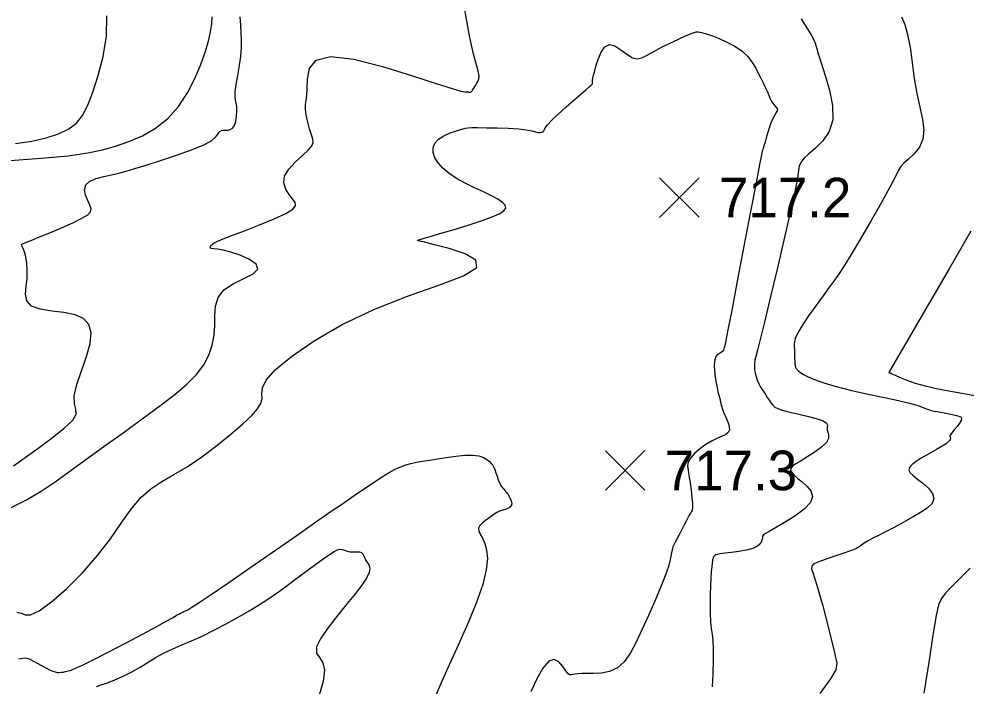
# Model space of a CAD drawing. Extents: x 2566142 to 2571431, y 418755 to 421584.
# Drawn here: x 2568476.3 to 2568835.3, y 420012.3 to 420265 of the extents above; entities that cross this region are included whole.
import ezdxf

# ---------------------------------------------------------------- set-up
doc = ezdxf.new("R2010")
doc.units = 0
for name, color, linetype in [('Contour_ADS_Major', 7, 'Continuous'), ('Contour_ADS_Minor', 7, 'Continuous'), ('Contour_ADS_Spot_Elevation', 7, 'Continuous')]:
    doc.layers.add(name, color=color, linetype=linetype)

# ---------------------------------------------------------------- blocks, each defined once
blk = doc.blocks.new('S750')
at = {"layer": 'Contour_ADS_Spot_Elevation'}
for p, q in [((-0.5, 0.498), (0.5, -0.498)), ((-0.498, -0.5), (0.498, 0.5))]:
    blk.add_line(p, q, dxfattribs=at)

msp = doc.modelspace()

# ---------------------------------------------------------------- linework, layer by layer
at = {"layer": 'Contour_ADS_Major'}
for points in [[(2568649.08, 420239.37), (2568649.47, 420239.97), (2568649.89, 420240.63), (2568650.3, 420241.37), (2568650.61, 420242.28), (2568650.69, 420243.51), (2568650.42, 420245.19), (2568649.72, 420247.61), (2568648.58, 420251.7), (2568647.04, 420258.56), (2568645.13, 420269.26)], [(2568772.83, 420265.1), (2568773.5, 420263.85), (2568774.43, 420262.35), (2568775.49, 420260.71), (2568776.55, 420259.02), (2568777.43, 420257.4), (2568778.05, 420255.89), (2568778.59, 420254.16), (2568779.28, 420251.79), (2568780.35, 420248.35), (2568781.92, 420243.6), (2568783.56, 420238.01), (2568784.68, 420232.2), (2568784.74, 420226.8), (2568783.35, 420222.33), (2568780.96, 420218.78), (2568778.2, 420216.01), (2568775.69, 420213.89), (2568773.95, 420212.28), (2568772.9, 420211.06), (2568772.34, 420210.1), (2568772.07, 420209.27), (2568771.91, 420208.45), (2568771.79, 420207.58), (2568771.67, 420206.59), (2568771.52, 420205.42), (2568771.27, 420203.88), (2568770.77, 420201.38), (2568769.86, 420197.18), (2568768.36, 420190.57), (2568766.19, 420181.2), (2568763.64, 420170.28), (2568761.07, 420159.38), (2568758.85, 420150.09), (2568757.25, 420143.61), (2568756.22, 420139.55), (2568755.61, 420137.18), (2568755.28, 420135.73), (2568755.1, 420134.55), (2568755.04, 420133.48), (2568755.09, 420132.45), (2568755.24, 420131.4), (2568755.47, 420130.28), (2568755.79, 420129.11), (2568756.2, 420127.95), (2568756.69, 420126.82), (2568757.27, 420125.76), (2568757.91, 420124.75), (2568758.58, 420123.74), (2568759.26, 420122.72), (2568759.93, 420121.66), (2568760.59, 420120.6), (2568761.28, 420119.6), (2568762, 420118.73), (2568762.82, 420118.01), (2568763.95, 420117.4), (2568765.6, 420116.8), (2568768.04, 420116.16), (2568771.34, 420115.4), (2568775.03, 420114.55), (2568778.49, 420113.66), (2568781.1, 420112.78), (2568782.44, 420111.94), (2568782.8, 420111.11), (2568782.68, 420110.27), (2568782.58, 420109.4), (2568782.85, 420108.44), (2568783.2, 420107.37), (2568783.2, 420106.11), (2568782.44, 420104.61), (2568780.64, 420102.87), (2568778.11, 420101.02)], [(2568473.18, 420079.81), (2568479.2, 420082.9), (2568484.76, 420086.18), (2568490.09, 420089.73), (2568495.59, 420093.66), (2568501.65, 420098.08), (2568508.51, 420103.03), (2568515.82, 420108.28), (2568523.05, 420113.52), (2568529.71, 420118.43), (2568535.36, 420122.8), (2568539.99, 420126.72), (2568543.65, 420130.38), (2568546.4, 420133.98), (2568548.34, 420137.64), (2568549.58, 420141.39), (2568550.26, 420145.17), (2568550.54, 420148.95), (2568550.61, 420152.68), (2568550.88, 420156.25), (2568551.85, 420159.52), (2568553.99, 420162.37), (2568557.5, 420164.73), (2568561.56, 420166.71), (2568565.04, 420168.48), (2568566.85, 420170.23), (2568566.22, 420172.07), (2568563.7, 420173.88), (2568560.2, 420175.48), (2568556.62, 420176.7), (2568553.7, 420177.41), (2568551.53, 420177.75), (2568550.05, 420177.91), (2568549.18, 420178.08), (2568548.85, 420178.4), (2568548.93, 420178.86), (2568549.31, 420179.36), (2568549.86, 420179.86), (2568550.53, 420180.3), (2568551.67, 420180.84), (2568553.69, 420181.66), (2568557.02, 420182.94), (2568561.86, 420184.78), (2568567.5, 420186.99), (2568573, 420189.26), (2568577.43, 420191.3), (2568580.08, 420192.91), (2568581.13, 420194.22), (2568580.98, 420195.46), (2568580.03, 420196.84), (2568578.69, 420198.54), (2568577.43, 420200.57), (2568576.72, 420202.88), (2568577.03, 420205.42), (2568578.65, 420208.13), (2568581.13, 420210.83), (2568583.81, 420213.32), (2568586.06, 420215.39), (2568587.38, 420216.94), (2568587.85, 420218.2), (2568587.7, 420219.49), (2568587.17, 420221.14), (2568586.48, 420223.36), (2568585.77, 420225.94), (2568585.19, 420228.54), (2568584.87, 420230.82), (2568584.9, 420232.58), (2568585.15, 420234.17), (2568585.44, 420236.06), (2568585.6, 420238.72), (2568585.65, 420242.36), (2568586.43, 420246.26), (2568589.01, 420249.4), (2568594.44, 420250.79), (2568603.28, 420249.78), (2568614.15, 420247.05), (2568625.15, 420243.64), (2568634.4, 420240.55), (2568640.5, 420238.6), (2568643.86, 420237.65), (2568645.37, 420237.36), (2568645.93, 420237.36), (2568646.27, 420237.37), (2568646.56, 420237.34), (2568646.8, 420237.29), (2568646.99, 420237.24), (2568647.15, 420237.21), (2568647.28, 420237.2), (2568647.39, 420237.21), (2568647.48, 420237.23), (2568647.57, 420237.26), (2568647.65, 420237.32), (2568647.73, 420237.4), (2568647.81, 420237.5), (2568647.92, 420237.64), (2568648.04, 420237.83), (2568648.22, 420238.08), (2568648.44, 420238.41), (2568648.73, 420238.85), (2568649.08, 420239.37)], [(2568778.11, 420101.02), (2568775.32, 420099.22), (2568772.76, 420097.66), (2568770.8, 420096.47), (2568769.5, 420095.55), (2568768.82, 420094.78), (2568768.73, 420094.02), (2568769.2, 420093.17), (2568770.14, 420092.16), (2568771.48, 420090.99), (2568773.14, 420089.63), (2568774.94, 420088.04), (2568776.44, 420086.23), (2568777.09, 420084.16), (2568776.36, 420081.83), (2568773.93, 420079.26), (2568770.37, 420076.65), (2568766.47, 420074.23), (2568763.03, 420072.25), (2568760.65, 420070.89), (2568759.25, 420070.04), (2568758.54, 420069.55), (2568758.25, 420069.27), (2568758.15, 420069.05), (2568758.12, 420068.8), (2568758.09, 420068.44), (2568758.01, 420067.89), (2568757.77, 420067.11), (2568757.23, 420066.19), (2568756.2, 420065.24), (2568754.51, 420064.4), (2568752.07, 420063.76), (2568749.2, 420063.29), (2568746.32, 420062.95), (2568743.86, 420062.68), (2568742.11, 420062.44), (2568741.02, 420062.2), (2568740.38, 420061.97), (2568740.01, 420061.73), (2568739.77, 420061.47), (2568739.6, 420061.21), (2568739.47, 420060.96), (2568739.38, 420060.74), (2568739.3, 420060.52), (2568739.22, 420060.22), (2568739.13, 420059.69), (2568739.02, 420058.83), (2568738.87, 420057.5), (2568738.71, 420055.68), (2568738.55, 420053.33), (2568738.42, 420050.41), (2568738.32, 420046.97), (2568738.28, 420043.29), (2568738.32, 420039.72), (2568738.47, 420036.6), (2568738.73, 420034.15), (2568739.04, 420031.98), (2568739.31, 420029.57), (2568739.46, 420026.38), (2568739.43, 420022.08), (2568739.26, 420017.09), (2568739.01, 420012)]]:
    msp.add_lwpolyline(points, dxfattribs=at)
at = {"layer": 'Contour_ADS_Minor'}
for points in [[(2568471.22, 420211.32), (2568484.79, 420212.23), (2568495.01, 420213.18), (2568502.39, 420214.24), (2568508, 420215.45), (2568512.91, 420216.88), (2568517.96, 420218.6), (2568523.12, 420220.78), (2568528.14, 420223.61), (2568532.76, 420227.27), (2568536.79, 420231.87), (2568540.2, 420237.08), (2568543, 420242.5), (2568545.23, 420247.73), (2568546.91, 420252.42), (2568548.11, 420256.54), (2568548.91, 420260.11), (2568549.39, 420263.16), (2568549.62, 420265.76)], [(2568475.04, 420217.84), (2568481.17, 420218.77), (2568486.64, 420219.97), (2568491.34, 420221.48), (2568495.18, 420223.32), (2568498.12, 420225.58), (2568500.42, 420228.48), (2568502.38, 420232.29), (2568504.31, 420237.26), (2568506.41, 420243.55), (2568508.31, 420250.79), (2568509.53, 420258.51), (2568509.61, 420266.23)], [(2568501.61, 420198.26), (2568501.23, 420200.32), (2568501.68, 420202.13), (2568503.24, 420203.52), (2568505.65, 420204.55), (2568508.52, 420205.33), (2568511.44, 420205.98), (2568514.15, 420206.61), (2568516.95, 420207.35), (2568520.27, 420208.32), (2568524.54, 420209.63), (2568529.98, 420211.36), (2568535.98, 420213.35), (2568541.73, 420215.41), (2568546.39, 420217.34), (2568549.39, 420218.98), (2568551, 420220.3), (2568551.73, 420221.31), (2568552.11, 420222.04), (2568552.54, 420222.49), (2568553.11, 420222.74), (2568553.81, 420222.84), (2568554.61, 420222.87), (2568555.51, 420222.89), (2568556.42, 420223.08), (2568557.28, 420223.6), (2568558, 420224.62), (2568558.52, 420226.22), (2568558.84, 420228.18), (2568558.96, 420230.18), (2568558.9, 420231.89), (2568558.68, 420233.13), (2568558.41, 420234.18), (2568558.25, 420235.45), (2568558.32, 420237.35), (2568558.71, 420240.16), (2568559.31, 420243.62), (2568559.94, 420247.33), (2568560.45, 420250.91), (2568560.7, 420254.07), (2568560.73, 420256.92), (2568560.61, 420259.69), (2568560.41, 420262.6), (2568560.19, 420265.83)], [(2568810.82, 420265.78), (2568812.04, 420262.94), (2568813.12, 420259.11), (2568814.03, 420254.17), (2568814.83, 420248.46), (2568815.65, 420242.49), (2568816.6, 420236.71), (2568817.71, 420231.53), (2568818.71, 420226.97), (2568819.23, 420222.98), (2568818.93, 420219.51), (2568817.6, 420216.5), (2568815.59, 420213.96), (2568813.41, 420211.87), (2568811.57, 420210.23), (2568810.4, 420208.95), (2568809.52, 420207.46), (2568808.38, 420205.13), (2568806.41, 420201.27), (2568803.25, 420195.54), (2568799.33, 420188.68), (2568795.29, 420181.74), (2568791.74, 420175.77), (2568789.12, 420171.51), (2568787.18, 420168.53), (2568785.47, 420166.1), (2568783.53, 420163.48), (2568781.06, 420160.13), (2568778.3, 420156.34), (2568775.61, 420152.55), (2568773.37, 420149.25), (2568771.87, 420146.79), (2568770.99, 420145.11), (2568770.56, 420144.01), (2568770.37, 420143.32), (2568770.26, 420142.86), (2568770.2, 420142.44), (2568770.17, 420141.89), (2568770.17, 420141.03), (2568770.19, 420139.74), (2568770.23, 420138.18), (2568770.29, 420136.61), (2568770.35, 420135.25), (2568770.41, 420134.29), (2568770.49, 420133.67), (2568770.58, 420133.29), (2568770.68, 420133.03), (2568770.8, 420132.81), (2568770.94, 420132.6), (2568771.08, 420132.39), (2568771.22, 420132.17), (2568771.39, 420131.94), (2568771.71, 420131.63), (2568772.35, 420131.17), (2568773.47, 420130.51), (2568775.24, 420129.59), (2568777.81, 420128.46), (2568781.36, 420127.16), (2568786.04, 420125.75), (2568791.86, 420124.29), (2568798.23, 420122.87), (2568804.41, 420121.56), (2568809.63, 420120.44), (2568813.36, 420119.59), (2568815.79, 420118.95), (2568817.33, 420118.47), (2568818.38, 420118.07), (2568819.29, 420117.7), (2568820.17, 420117.36), (2568821.07, 420117.04), (2568822.06, 420116.75), (2568823.17, 420116.49), (2568824.38, 420116.26)], [(2568693.21, 420239.96), (2568693.57, 420240.35), (2568693.72, 420240.61), (2568693.75, 420240.85), (2568693.73, 420241.18), (2568693.75, 420241.72), (2568693.86, 420242.56), (2568694.11, 420243.76), (2568694.52, 420245.38), (2568695.12, 420247.47), (2568695.93, 420249.98), (2568697, 420252.48), (2568698.37, 420254.44), (2568700.08, 420255.33), (2568702.15, 420254.82), (2568704.42, 420253.37), (2568706.7, 420251.64), (2568708.81, 420250.29), (2568710.64, 420249.84), (2568712.4, 420250.22), (2568714.38, 420251.24), (2568716.88, 420252.7), (2568720.05, 420254.39), (2568723.58, 420256.13), (2568727, 420257.71), (2568729.85, 420258.96), (2568731.82, 420259.72), (2568733.04, 420260.07), (2568733.79, 420260.14), (2568734.37, 420260.06), (2568735.01, 420259.92), (2568735.91, 420259.68), (2568737.23, 420259.27), (2568739.14, 420258.59), (2568741.7, 420257.58), (2568744.66, 420256.27), (2568747.68, 420254.67), (2568750.4, 420252.82), (2568752.58, 420250.75), (2568754.26, 420248.57), (2568755.58, 420246.37), (2568756.67, 420244.25), (2568757.66, 420242.3), (2568758.55, 420240.54), (2568759.31, 420238.97), (2568759.92, 420237.6), (2568760.37, 420236.41), (2568760.75, 420235.37), (2568761.14, 420234.45), (2568761.62, 420233.59), (2568762.25, 420232.77), (2568762.92, 420232), (2568763.47, 420231.31), (2568763.78, 420230.72), (2568763.71, 420230.22), (2568763.34, 420229.63), (2568762.74, 420228.73), (2568762, 420227.32), (2568761.2, 420225.28), (2568760.41, 420222.86), (2568759.69, 420220.43), (2568759.1, 420218.36), (2568758.67, 420216.92), (2568758.38, 420216.03), (2568758.21, 420215.54), (2568758.1, 420215.29), (2568758.01, 420214.95), (2568757.73, 420213.55), (2568757.03, 420209.93), (2568755.71, 420202.97), (2568753.63, 420192.07), (2568751.11, 420178.89), (2568748.57, 420165.63), (2568746.44, 420154.51), (2568745.03, 420147.2), (2568744.23, 420143.15), (2568743.84, 420141.29), (2568743.66, 420140.54), (2568743.5, 420140.01), (2568743.29, 420139.52), (2568742.97, 420139.07), (2568742.49, 420138.69), (2568741.83, 420138.34), (2568741.11, 420137.87), (2568740.45, 420137.1), (2568740, 420135.84), (2568739.85, 420133.98), (2568739.96, 420131.72), (2568740.23, 420129.35), (2568740.57, 420127.15), (2568740.92, 420125.32), (2568741.25, 420123.81), (2568741.59, 420122.47), (2568741.92, 420121.19), (2568742.25, 420119.85), (2568742.59, 420118.51), (2568742.94, 420117.23), (2568743.3, 420116.11), (2568743.67, 420115.17), (2568744.05, 420114.36), (2568744.44, 420113.56)], [(2568500.41, 420055.25), (2568506.11, 420061.73), (2568510.97, 420068.11), (2568515.12, 420074.06), (2568518.87, 420079.35), (2568522.52, 420083.73), (2568526.34, 420087.07), (2568530.48, 420089.79), (2568535.02, 420092.39), (2568540.07, 420095.4), (2568545.63, 420099.19), (2568551.32, 420103.47), (2568556.67, 420107.78), (2568561.21, 420111.67), (2568564.56, 420114.81), (2568566.78, 420117.29), (2568568.03, 420119.34), (2568568.48, 420121.18), (2568568.41, 420123.04), (2568568.61, 420125.25), (2568569.97, 420128.14), (2568573.42, 420132.05), (2568579.61, 420137.18), (2568588.27, 420143.1), (2568598.86, 420149.23), (2568610.86, 420155.01), (2568623.56, 420159.96), (2568635.42, 420164.15), (2568644.75, 420167.72), (2568649.82, 420170.83), (2568649.54, 420173.61), (2568645.39, 420176.03), (2568639.44, 420178.01), (2568633.79, 420179.48), (2568630.07, 420180.4), (2568628.15, 420180.88), (2568627.43, 420181.07), (2568627.33, 420181.11), (2568627.34, 420181.13), (2568627.38, 420181.15), (2568627.45, 420181.18), (2568627.56, 420181.22), (2568627.77, 420181.3), (2568628.42, 420181.5), (2568629.89, 420181.94), (2568632.58, 420182.73), (2568636.7, 420183.94), (2568641.74, 420185.44), (2568647.01, 420187.06), (2568651.83, 420188.62), (2568655.64, 420190), (2568658.36, 420191.21), (2568660.06, 420192.31), (2568660.8, 420193.36), (2568660.64, 420194.41), (2568659.65, 420195.51), (2568657.88, 420196.69), (2568655.42, 420198), (2568652.35, 420199.47), (2568648.92, 420201.08), (2568645.42, 420202.8), (2568642.14, 420204.63), (2568639.3, 420206.53), (2568636.97, 420208.49), (2568635.19, 420210.46), (2568633.96, 420212.43), (2568633.31, 420214.37), (2568633.3, 420216.23), (2568633.95, 420217.95), (2568635.32, 420219.49), (2568637.38, 420220.79), (2568639.8, 420221.86), (2568642.21, 420222.68), (2568644.2, 420223.26), (2568645.54, 420223.62), (2568646.62, 420223.79), (2568647.98, 420223.84), (2568650.16, 420223.83), (2568653.51, 420223.8), (2568657.62, 420223.73), (2568661.88, 420223.6), (2568665.7, 420223.36), (2568668.6, 420223.02), (2568670.67, 420222.63), (2568672.11, 420222.28), (2568673.14, 420222.04), (2568673.94, 420221.98), (2568674.56, 420222.09), (2568675, 420222.34), (2568675.28, 420222.68), (2568675.47, 420223.13), (2568675.82, 420223.81), (2568676.6, 420224.9), (2568678.12, 420226.55), (2568680.55, 420228.85), (2568683.53, 420231.53), (2568686.6, 420234.21), (2568689.29, 420236.52), (2568691.23, 420238.2), (2568692.48, 420239.29), (2568693.21, 420239.96)], [(2568474.29, 420095.72), (2568476.42, 420097.23), (2568479.6, 420099.5), (2568484.02, 420102.66), (2568488.97, 420106.32), (2568493.51, 420109.96), (2568496.72, 420113.06), (2568497.98, 420115.31), (2568497.88, 420117.15), (2568497.34, 420119.23), (2568497.26, 420122.2), (2568498.31, 420126.49), (2568500.1, 420131.68), (2568501.99, 420137.1), (2568503.35, 420142.1), (2568503.66, 420146.17), (2568502.8, 420149.26), (2568500.77, 420151.5), (2568497.59, 420152.96), (2568493.38, 420153.81), (2568488.74, 420154.37), (2568484.4, 420155.05), (2568481.1, 420156.22), (2568479.36, 420158.17), (2568478.85, 420160.74), (2568479.04, 420163.71), (2568479.41, 420166.8), (2568479.51, 420169.8), (2568479.33, 420172.55), (2568478.94, 420174.92), (2568478.45, 420176.78), (2568477.92, 420178.05), (2568477.49, 420178.84), (2568477.27, 420179.32), (2568477.39, 420179.65), (2568477.98, 420180), (2568479.2, 420180.5), (2568481.2, 420181.26), (2568484.14, 420182.42), (2568488.06, 420184.02), (2568492.46, 420185.9), (2568496.71, 420187.8), (2568500.19, 420189.49), (2568502.42, 420190.81), (2568503.51, 420191.91), (2568503.7, 420193.04), (2568503.25, 420194.42), (2568502.42, 420196.22), (2568501.61, 420198.26)], [(2568837.09, 420184.57), (2568828.83, 420170.34), (2568820.56, 420156.13), (2568813.69, 420144.34), (2568809.29, 420136.79), (2568807.01, 420132.88), (2568806.17, 420131.39), (2568806.06, 420131.12), (2568806.15, 420131.05), (2568806.45, 420130.9), (2568807.14, 420130.6), (2568808.36, 420130.06), (2568810.26, 420129.24), (2568812.83, 420128.22), (2568816.01, 420127.1), (2568819.77, 420126.01), (2568824.05, 420125.02), (2568828.71, 420124.11), (2568833.61, 420123.23), (2568838.59, 420122.34)], [(2568824.38, 420116.26), (2568825.65, 420116.03), (2568826.94, 420115.8), (2568828.22, 420115.56), (2568829.45, 420115.3), (2568830.61, 420115.05), (2568831.67, 420114.81), (2568832.59, 420114.56), (2568833.26, 420114.24), (2568833.59, 420113.73), (2568833.46, 420112.96), (2568832.81, 420111.86), (2568831.84, 420110.58), (2568830.79, 420109.31), (2568829.9, 420108.24), (2568829.36, 420107.51), (2568829.13, 420107.06), (2568829.11, 420106.8), (2568829.19, 420106.63), (2568829.29, 420106.46), (2568829.36, 420106.26), (2568829.36, 420106.02), (2568829.24, 420105.7), (2568828.97, 420105.3), (2568828.51, 420104.81), (2568827.81, 420104.23), (2568826.83, 420103.55), (2568825.55, 420102.77), (2568824.01, 420101.89), (2568822.24, 420100.91), (2568820.31, 420099.82), (2568818.3, 420098.64), (2568816.39, 420097.42), (2568814.84, 420096.22), (2568813.85, 420095.1), (2568813.61, 420094.1), (2568814.09, 420093.12), (2568815.21, 420092.03), (2568816.87, 420090.73), (2568818.94, 420089.11), (2568820.98, 420087.26), (2568822.53, 420085.3), (2568823.11, 420083.33), (2568822.37, 420081.46), (2568820.55, 420079.69), (2568818.03, 420078), (2568815.2, 420076.37), (2568812.36, 420074.81), (2568809.61, 420073.31), (2568806.96, 420071.9), (2568804.44, 420070.58), (2568802.08, 420069.37), (2568799.94, 420068.27), (2568798.12, 420067.3), (2568796.69, 420066.46), (2568795.66, 420065.73), (2568794.71, 420065.05), (2568793.45, 420064.33), (2568791.5, 420063.49), (2568788.62, 420062.46), (2568785.22, 420061.34), (2568781.87, 420060.23), (2568779.15, 420059.26), (2568777.49, 420058.48), (2568776.77, 420057.72), (2568776.75, 420056.75), (2568777.18, 420055.33), (2568777.86, 420053.28), (2568778.72, 420050.52), (2568779.75, 420047.01), (2568780.93, 420042.74), (2568782.22, 420037.77), (2568783.52, 420032.56), (2568784.72, 420027.69), (2568785.7, 420023.73), (2568786.26, 420020.95), (2568785.88, 420018.44), (2568783.93, 420015), (2568779.82, 420009.43)], [(2568744.44, 420113.56), (2568744.86, 420112.67), (2568745.26, 420111.61), (2568745.55, 420110.46), (2568745.56, 420109.34), (2568745.17, 420108.37), (2568744.27, 420107.62), (2568742.89, 420106.95), (2568741.12, 420106.2), (2568739.02, 420105.18), (2568736.71, 420103.78), (2568734.4, 420102.12), (2568732.36, 420100.36), (2568730.83, 420098.69), (2568730, 420097.21), (2568729.75, 420095.76), (2568729.9, 420094.12), (2568730.26, 420092.05), (2568730.68, 420089.44), (2568731.06, 420086.55), (2568731.37, 420083.77), (2568731.55, 420081.47), (2568731.56, 420079.93), (2568731.41, 420078.97), (2568731.14, 420078.33), (2568730.78, 420077.75), (2568730.34, 420076.99), (2568729.82, 420076), (2568729.19, 420074.78), (2568728.44, 420073.32), (2568727.56, 420071.64), (2568726.63, 420069.88), (2568725.74, 420068.22), (2568725.01, 420066.84), (2568724.51, 420065.84), (2568724.18, 420065.07), (2568723.96, 420064.34), (2568723.79, 420063.42), (2568723.57, 420062.11), (2568723.17, 420060.23), (2568722.45, 420057.63), (2568721.26, 420054.12), (2568719.51, 420049.65), (2568717.35, 420044.5), (2568714.98, 420039.09), (2568712.58, 420033.8), (2568710.31, 420029), (2568708.07, 420024.87), (2568705.72, 420021.55), (2568703.12, 420019.16), (2568700.19, 420017.78), (2568697.12, 420017.18), (2568694.17, 420017.06), (2568691.6, 420017.12), (2568689.6, 420017.11), (2568688.11, 420017), (2568687.03, 420016.85), (2568686.24, 420016.66), (2568685.61, 420016.51), (2568685.04, 420016.57), (2568684.4, 420017.03), (2568683.56, 420018.09), (2568682.42, 420019.78), (2568680.96, 420021.48), (2568679.21, 420022.4), (2568677.16, 420021.75), (2568674.85, 420019.03), (2568672.49, 420014.84), (2568670.3, 420010.08)], [(2568476.33, 420022.68), (2568477.11, 420022.81), (2568477.86, 420022.91), (2568478.54, 420022.94), (2568479.18, 420022.89), (2568479.86, 420022.7), (2568480.69, 420022.34), (2568481.79, 420021.78), (2568483.21, 420021), (2568484.83, 420020.11), (2568486.46, 420019.23), (2568487.94, 420018.48), (2568489.12, 420017.96), (2568490.06, 420017.66), (2568490.85, 420017.51), (2568491.58, 420017.48), (2568492.34, 420017.52), (2568493.15, 420017.62), (2568494.03, 420017.79), (2568494.99, 420018.03), (2568496.12, 420018.38), (2568497.79, 420019.04), (2568500.42, 420020.24), (2568504.46, 420022.23), (2568510.11, 420025.12), (2568516.66, 420028.53), (2568523.15, 420031.96), (2568528.65, 420034.92), (2568532.44, 420037.01), (2568534.76, 420038.34), (2568536.08, 420039.13), (2568536.87, 420039.6), (2568537.52, 420039.94), (2568538.15, 420040.23), (2568538.79, 420040.5), (2568539.47, 420040.81), (2568540.32, 420041.24), (2568541.83, 420042.16), (2568544.59, 420043.95), (2568549.17, 420047.03), (2568555.87, 420051.6), (2568563.82, 420057.06), (2568571.88, 420062.62), (2568578.89, 420067.48), (2568583.98, 420071.03), (2568587.41, 420073.46), (2568589.76, 420075.14), (2568591.59, 420076.43), (2568593.37, 420077.66), (2568595.37, 420079.01), (2568597.76, 420080.62), (2568600.71, 420082.63), (2568604.31, 420085.09), (2568608.28, 420087.79), (2568612.22, 420090.41), (2568615.76, 420092.65), (2568618.62, 420094.3), (2568620.94, 420095.41), (2568622.95, 420096.15), (2568624.89, 420096.66), (2568626.99, 420097.08), (2568629.32, 420097.47), (2568631.97, 420097.88), (2568634.99, 420098.35), (2568638.39, 420098.89), (2568641.93, 420099.4), (2568645.34, 420099.75), (2568648.32, 420099.81), (2568650.65, 420099.48), (2568652.39, 420098.86), (2568653.67, 420098.09), (2568654.6, 420097.32), (2568655.32, 420096.63), (2568655.88, 420095.97)], [(2568655.88, 420095.97), (2568656.34, 420095.24), (2568656.73, 420094.31), (2568657.1, 420093.14), (2568657.51, 420091.79), (2568657.98, 420090.4), (2568658.56, 420089.08), (2568659.26, 420087.92), (2568660.06, 420086.88), (2568660.89, 420085.87), (2568661.69, 420084.81), (2568662.4, 420083.65), (2568662.92, 420082.47), (2568663.11, 420081.37), (2568662.87, 420080.46), (2568662.12, 420079.79), (2568661, 420079.32), (2568659.72, 420078.93), (2568658.47, 420078.52), (2568657.4, 420078.02), (2568656.43, 420077.41), (2568655.48, 420076.71), (2568654.42, 420075.92), (2568653.21, 420075.06), (2568652, 420074.13), (2568651.03, 420073.15), (2568650.51, 420072.13), (2568650.59, 420071.05), (2568651.14, 420069.81), (2568651.96, 420068.29), (2568652.84, 420066.36), (2568653.55, 420063.88), (2568653.85, 420060.61), (2568653.46, 420056.31), (2568652.1, 420050.73), (2568649.64, 420043.76), (2568646.42, 420035.97), (2568642.89, 420028.03), (2568639.54, 420020.65), (2568636.73, 420014.37), (2568634.47, 420009.07)], [(2568505.78, 420012.12), (2568507.5, 420012.72), (2568509.86, 420013.59), (2568512.72, 420014.71), (2568515.87, 420016.08), (2568519.09, 420017.67), (2568522.22, 420019.46), (2568525.27, 420021.34), (2568528.31, 420023.2), (2568531.4, 420024.93), (2568534.61, 420026.45), (2568538.01, 420027.89), (2568541.71, 420029.43), (2568545.78, 420031.23), (2568550.25, 420033.42), (2568554.9, 420035.86), (2568559.43, 420038.37), (2568563.57, 420040.78), (2568567.13, 420042.96), (2568570.32, 420045.03), (2568573.44, 420047.18), (2568576.8, 420049.58), (2568580.6, 420052.36), (2568584.59, 420055.29), (2568588.39, 420058.09), (2568591.63, 420060.46), (2568594.05, 420062.2), (2568595.77, 420063.33), (2568597, 420063.94), (2568597.96, 420064.15), (2568598.84, 420064.05), (2568599.72, 420063.77), (2568600.67, 420063.44), (2568601.72, 420063.21), (2568602.91, 420063.16), (2568604.13, 420063.19), (2568605.25, 420063.17), (2568606.14, 420062.94), (2568606.72, 420062.42), (2568607.09, 420061.65), (2568607.41, 420060.76), (2568607.83, 420059.84), (2568608.43, 420058.97), (2568609.02, 420058.02), (2568609.32, 420056.85), (2568609.07, 420055.29), (2568608.06, 420053.22), (2568606.28, 420050.59), (2568603.82, 420047.37), (2568600.72, 420043.55), (2568597.16, 420039.19), (2568593.64, 420034.68), (2568590.77, 420030.5), (2568589.15, 420027.12), (2568589.15, 420024.83), (2568590.19, 420023.09), (2568591.47, 420021.17), (2568592.16, 420018.33), (2568591.65, 420014.08), (2568590.11, 420008.8)], [(2568836.81, 420056.96), (2568834.46, 420054.62), (2568831.9, 420052.08), (2568829.44, 420049.59), (2568827.37, 420047.39), (2568825.92, 420045.51), (2568824.87, 420043.08), (2568823.93, 420039.04), (2568822.8, 420032.29), (2568821.24, 420022.17), (2568819.29, 420009.57)], [(2568475.49, 420040.35), (2568477.12, 420039.96), (2568478.68, 420039.35), (2568480.77, 420039.35), (2568483.97, 420040.76), (2568488.66, 420044.16), (2568494.36, 420049.19), (2568500.41, 420055.25)]]:
    msp.add_lwpolyline(points, dxfattribs=at)

# ---------------------------------------------------------------- block references
at = {"layer": 'Contour_ADS_Spot_Elevation', "xscale": 15, "yscale": 15}
for p in [(2568726.61, 420197.35), (2568706.07, 420094)]:
    msp.add_blockref('S750', p, dxfattribs=at)

# ---------------------------------------------------------------- texts
at = {"layer": 'Contour_ADS_Spot_Elevation'}
for s, p in [('717.2', (2568741.61, 420189.85)), ('717.3', (2568721.07, 420086.5))]:
    msp.add_text(s, height=15, dxfattribs=at).set_placement(p)

doc.saveas('drawing.dxf')
